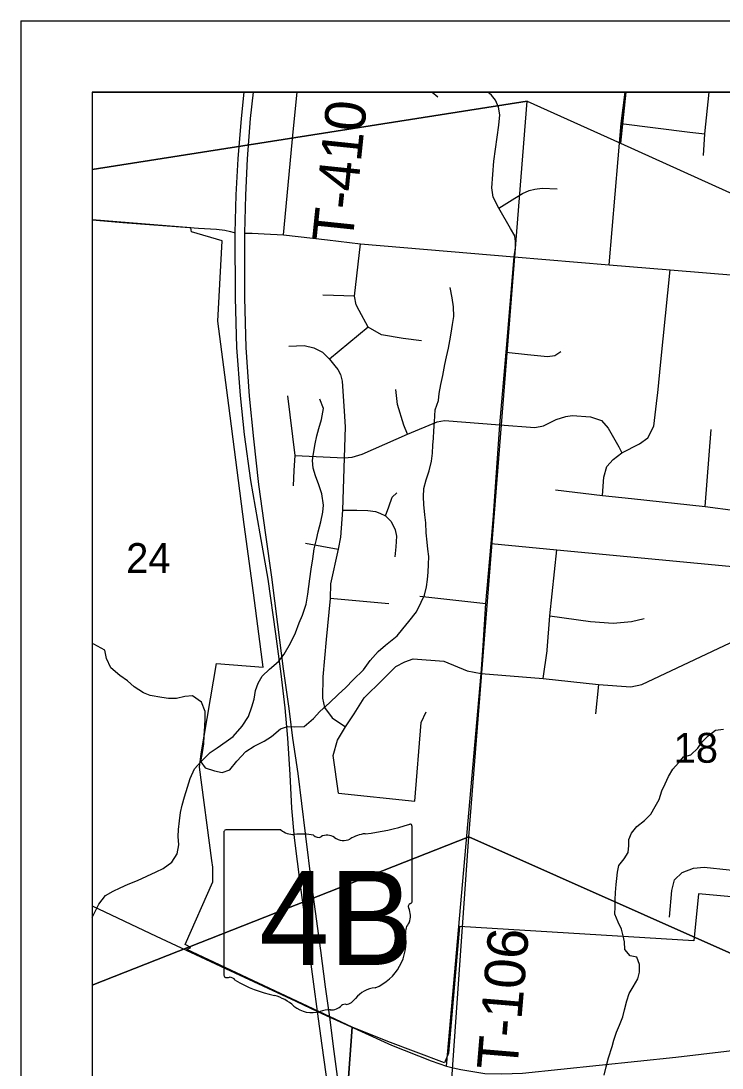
# Model space of a CAD drawing. Extents: x 0 to 34, y 0 to 22.
# Drawn here: x 2 to 2.983, y 19.532 to 21 of the extents above; entities that cross this region are included whole.
import ezdxf

# ---------------------------------------------------------------- set-up
doc = ezdxf.new("R2010")
doc.units = 0
for name, color, linetype in [('Default', 7, 'Continuous'), ('GM_X_County_Road', 7, 'Continuous'), ('GM_X_Minor_River', 7, 'Continuous'), ('GM_X_Section', 7, 'Continuous'), ('GM_X_Section_Text', 7, 'Continuous'), ('GM_X_State_Location', 7, 'Continuous'), ('GM_X_State_Route', 7, 'Continuous'), ('GM_X_State_Shield', 7, 'Continuous'), ('GM_X_Township_Road', 7, 'Continuous'), ('GM_X_Township_Road_Text', 7, 'Continuous'), ('SH_Cut_Line', 7, 'Continuous'), ('SH_Data', 7, 'Continuous')]:
    doc.layers.add(name, color=color, linetype=linetype)

msp = doc.modelspace()

# ---------------------------------------------------------------- linework, layer by layer
at = {"layer": 'Default'}
for points in [[(2.848, 20.9), (2.1, 20.9), (2.1, 20.7916), (2.7095, 20.8874), (2.8405, 20.8285)], [(3.8452, 20.9), (2.848, 20.9), (2.8405, 20.8285), (3.806, 20.3918)], [(2.1, 20.7916), (2.1, 19.6477), (2.6281, 19.856), (2.7095, 20.8874)]]:
    msp.add_lwpolyline(points, close=True, dxfattribs=at)
for points in [[(2.4657, 19.3633), (2.4543, 19.4479), (2.4643, 19.5889), (2.2326, 19.6977), (2.2384, 19.7007), (2.2301, 19.7049), (2.2689, 19.7927), (2.2692, 19.8013), (2.2689, 19.8136), (2.2677, 19.8229), (2.2505, 19.9535), (2.2526, 19.9723), (2.2744, 20.0988), (2.3397, 20.0939), (2.3259, 20.1979), (2.313, 20.2941), (2.2914, 20.4608), (2.2761, 20.579), (2.2821, 20.6918), (2.2391, 20.7041), (2.238, 20.7101), (2.1, 20.7213), (2.1, 19.3633)], [(2.5933, 19.3633), (2.6281, 19.856), (2.1, 19.6477), (2.1, 19.3633)], [(3.2168, 19.7517), (2.95, 19.7758), (2.9434, 19.7099), (2.6148, 19.7304), (2.5993, 19.5526), (2.5939, 19.5391), (2.5143, 19.569), (2.4643, 19.5889), (2.4543, 19.4479)]]:
    msp.add_lwpolyline(points, dxfattribs=at)
at = {"layer": 'GM_X_County_Road'}
for p, q in [((2.1, 20.7212), (2.143, 20.7174)), ((2.416, 19.6111), (2.433, 19.603)), ((2.433, 19.603), (2.4712, 19.5858))]:
    msp.add_line(p, q, dxfattribs=at)
for points in [[(2.143, 20.7174), (2.1677, 20.7153), (2.2489, 20.7094), (2.2744, 20.708), (2.286, 20.7066), (2.2939, 20.7047), (2.3004, 20.7028)], [(2.3138, 20.7026), (2.324, 20.7022), (2.3411, 20.7015), (2.3683, 20.7001), (2.4299, 20.6929)], [(2.4299, 20.6929), (2.4761, 20.6875), (2.6915, 20.6692), (2.8247, 20.6581)], [(2.8247, 20.6581), (2.9104, 20.6511), (3.1936, 20.6276), (3.2344, 20.6247), (3.2635, 20.6211), (3.2805, 20.6179), (3.3054, 20.6092), (3.3268, 20.6005), (3.4215, 20.5582), (3.4671, 20.5379), (3.6399, 20.4609), (3.6591, 20.4516), (3.6689, 20.4477), (3.679, 20.4455)], [(2.1, 19.7592), (2.1895, 19.7168), (2.287, 19.6714)], [(2.287, 19.6714), (2.3854, 19.6255), (2.416, 19.6111)], [(2.4712, 19.5858), (2.4721, 19.5853), (2.5194, 19.564), (2.5751, 19.5418), (2.5966, 19.5342), (2.6061, 19.5319)], [(2.6061, 19.5319), (2.6167, 19.5295), (2.6506, 19.5239), (2.6743, 19.5237), (2.703, 19.5246), (2.918, 19.5471), (3.06, 19.5636), (3.1002, 19.5668)]]:
    msp.add_lwpolyline(points, dxfattribs=at)
at = {"layer": 'GM_X_Minor_River'}
for points in [[(2.58, 20.4377), (2.5807, 20.4546), (2.5853, 20.4677), (2.5863, 20.4776), (2.5886, 20.49), (2.5917, 20.5028), (2.5944, 20.5183), (2.5967, 20.5289), (2.5993, 20.5413), (2.6012, 20.5515), (2.603, 20.5621), (2.6049, 20.5745), (2.6068, 20.5855), (2.6064, 20.5992), (2.6046, 20.6118), (2.602, 20.6263)], [(2.4216, 20.4413), (2.4241, 20.4564), (2.4192, 20.4695)], [(2.4234, 20.3111), (2.4244, 20.3209), (2.4218, 20.337), (2.4176, 20.3496), (2.413, 20.3623), (2.4099, 20.3727), (2.4086, 20.3838), (2.41, 20.3936), (2.4127, 20.4072), (2.4149, 20.4182), (2.4175, 20.4284), (2.4216, 20.4413)], [(2.2522, 19.961), (2.2584, 19.9525), (2.2712, 19.9487), (2.2822, 19.9461), (2.2929, 19.95), (2.3028, 19.9619), (2.3153, 19.9757), (2.3269, 19.983), (2.3412, 19.9902), (2.3512, 19.9964), (2.3641, 20.0075), (2.3737, 20.0106), (2.3839, 20.01), (2.3972, 20.0104), (2.4101, 20.0218), (2.4191, 20.0319), (2.4327, 20.044), (2.4448, 20.0555), (2.4553, 20.0651), (2.4659, 20.0759), (2.4804, 20.0899), (2.4895, 20.103), (2.5008, 20.1156), (2.5113, 20.1245), (2.5273, 20.1378), (2.5352, 20.1474), (2.5438, 20.1579), (2.5548, 20.1716), (2.5613, 20.1848), (2.5657, 20.1949), (2.5687, 20.2067), (2.5701, 20.2169), (2.5708, 20.2272), (2.5715, 20.2378), (2.5718, 20.2492), (2.5705, 20.2595), (2.5693, 20.2691), (2.5681, 20.2824), (2.5678, 20.2961), (2.5662, 20.3076), (2.565, 20.3217), (2.5642, 20.3327), (2.5649, 20.3445), (2.5679, 20.3566), (2.5724, 20.3691), (2.5755, 20.3827), (2.5769, 20.3941), (2.5776, 20.4051), (2.5786, 20.4149), (2.5789, 20.4252), (2.58, 20.4377)], [(2.1, 19.7426), (2.1091, 19.7617), (2.1186, 19.7736), (2.1294, 19.7798), (2.139, 19.7845), (2.1505, 19.7895), (2.1636, 19.7948), (2.1767, 19.8006), (2.1898, 19.8067), (2.1994, 19.8117), (2.2114, 19.8205), (2.219, 19.8321), (2.2212, 19.8446), (2.2204, 19.8565), (2.2207, 19.8663), (2.2222, 19.8785), (2.2236, 19.8902), (2.2262, 19.9004), (2.2295, 19.9118), (2.2333, 19.9254), (2.2371, 19.9378), (2.2432, 19.9514), (2.2522, 19.961), (2.2655, 19.9744), (2.2752, 19.9809), (2.2879, 19.9897), (2.2976, 19.9967), (2.3102, 20.0112), (2.3189, 20.0247), (2.3239, 20.0382), (2.3268, 20.0488), (2.329, 20.0609), (2.3324, 20.0715), (2.3384, 20.0812), (2.3485, 20.0908), (2.361, 20.1019), (2.3692, 20.112), (2.378, 20.1273), (2.3849, 20.142), (2.3902, 20.1559), (2.3947, 20.1668), (2.3997, 20.1823), (2.402, 20.1963), (2.4038, 20.2069), (2.4048, 20.2179), (2.4067, 20.2312), (2.409, 20.2456), (2.4109, 20.2596), (2.4143, 20.2729), (2.4169, 20.2838), (2.4203, 20.2978), (2.4234, 20.3111)], [(2.2522, 19.961), (2.2544, 19.9743), (2.2563, 19.9864), (2.257, 19.9982), (2.2577, 20.0107), (2.2584, 20.0214), (2.2583, 20.0316), (2.253, 20.0447), (2.2403, 20.0538), (2.23, 20.0529), (2.2181, 20.0498), (2.2067, 20.0501), (2.1973, 20.0512), (2.1814, 20.0543), (2.1716, 20.0579), (2.1589, 20.0663), (2.1493, 20.0745), (2.1388, 20.082), (2.1258, 20.0927), (2.1201, 20.1058), (2.1178, 20.1176), (2.102, 20.126), (2.1, 20.1271)], [(2.8176, 19.5216), (2.8206, 19.5333), (2.8237, 19.5461), (2.8287, 19.5619), (2.8312, 19.5706), (2.835, 19.5819), (2.8394, 19.592), (2.844, 19.6033), (2.8462, 19.6131), (2.8496, 19.6259), (2.8529, 19.6361), (2.8585, 19.6454), (2.8649, 19.6566), (2.8671, 19.666), (2.8674, 19.677), (2.8635, 19.687), (2.8541, 19.6889), (2.8467, 19.6978), (2.8463, 19.7085), (2.8443, 19.7173), (2.8419, 19.7265), (2.8372, 19.7361), (2.8326, 19.7473), (2.8333, 19.7579), (2.8332, 19.7678), (2.8335, 19.778), (2.8346, 19.789), (2.8356, 19.7977), (2.8363, 19.8065), (2.8381, 19.8159), (2.8456, 19.8252), (2.8511, 19.8341), (2.8522, 19.8436), (2.8521, 19.8524), (2.8561, 19.861), (2.8636, 19.8703), (2.8741, 19.8787), (2.8831, 19.8875), (2.8891, 19.8984), (2.8948, 19.9084), (2.8985, 19.9205), (2.903, 19.9302), (2.9079, 19.9407), (2.9139, 19.9508), (2.9221, 19.9597), (2.9288, 19.9682), (2.9392, 19.9709), (2.949, 19.9802), (2.9553, 19.9891), (2.9635, 19.9976), (2.9736, 20.0056), (2.9851, 20.0068)]]:
    msp.add_lwpolyline(points, dxfattribs=at)
at = {"layer": 'GM_X_Section'}
msp.add_lwpolyline([(2.7095, 20.8874), (2.8405, 20.8285), (3.806, 20.3918), (3.7257, 19.3674), (2.6281, 19.856)], close=True, dxfattribs=at)
msp.add_lwpolyline([(2.5933, 19.3633), (2.6281, 19.856), (3.7257, 19.3674), (3.7253, 19.3633)], dxfattribs=at)
at = {"layer": 'GM_X_State_Route'}
for points in [[(2.416, 19.6111), (2.4107, 19.6494), (2.4036, 19.7021), (2.392, 19.7883), (2.3837, 19.8543), (2.3798, 19.8963), (2.3774, 19.9434), (2.3743, 19.9941), (2.3703, 20.0368), (2.3646, 20.0846), (2.3573, 20.1404), (2.3464, 20.217), (2.3354, 20.2806), (2.3224, 20.3556), (2.3134, 20.4202), (2.3078, 20.4747), (2.3026, 20.5422), (2.3006, 20.6116), (2.3004, 20.7028), (2.3018, 20.7561), (2.3045, 20.8066), (2.3093, 20.8634), (2.3128, 20.9)], [(2.4129, 19.7512), (2.4078, 19.7888), (2.399, 19.8604), (2.3886, 19.9446), (2.381, 19.9942), (2.3762, 20.0358), (2.3683, 20.0917), (2.3602, 20.1535), (2.3516, 20.2202), (2.3435, 20.2792), (2.3336, 20.3501), (2.3264, 20.4142), (2.3206, 20.4737), (2.3159, 20.5421), (2.3139, 20.6115), (2.3138, 20.7026), (2.3151, 20.7559), (2.3178, 20.8065), (2.3219, 20.8632), (2.3259, 20.9)], [(2.4316, 19.6129), (2.427, 19.6456), (2.4203, 19.6967), (2.4129, 19.7512)], [(2.4541, 19.3633), (2.4449, 19.4144), (2.4331, 19.4862), (2.4223, 19.5631), (2.416, 19.6111)], [(2.4525, 19.4538), (2.4492, 19.4777), (2.4393, 19.5551), (2.433, 19.603), (2.4316, 19.6129)]]:
    msp.add_lwpolyline(points, dxfattribs=at)
at = {"layer": 'GM_X_State_Shield'}
for p, q in [((2.5483, 19.7659), (2.5483, 19.8706)), ((2.2846, 19.8622), (2.2846, 19.662)), ((2.3644, 19.8656), (2.2872, 19.8656)), ((2.5483, 19.7659), (2.5483, 19.7659))]:
    msp.add_line(p, q, dxfattribs=at)
for centre, radius, start, end in [((2.4544, 20.1384), 0.2796, 275.8445, 288.9065), ((2.5454, 19.871), 0.00294, 351.8621, 97.738), ((2.2876, 19.8626), 0.00305, 98.1301, 188.1301), ((2.3828, 19.8888), 0.0296, 231.6195, 271.1119), ((2.3926, 19.7533), 0.1064, 80.4867, 94.9883), ((2.4168, 19.8636), 0.00855, 219.7921, 297.1024), ((2.4293, 19.8405), 0.0178, 54.4667, 119.1411), ((2.4523, 19.8722), 0.0214, 233.8562, 294.8282), ((2.49, 19.8045), 0.0563, 97.3462, 120.7689), ((2.5452, 19.7655), 0.00314, 289.6038, 7.7341), ((2.5476, 19.7582), 0.00454, 107.944, 210.337), ((2.5187, 19.745), 0.0273, 340.033, 23.6496), ((2.5588, 19.7221), 0.0198, 136.8065, 186.9296), ((2.47, 19.7088), 0.0699, 292.3089, 8.9858), ((2.2877, 19.6616), 0.00308, 171.9584, 258.3066), ((2.2881, 19.6821), 0.0235, 267.339, 280.6039), ((2.2929, 19.6505), 0.00848, 29.7484, 93.2717), ((2.4, 19.8303), 0.2019, 240.4129, 257.1985), ((2.3398, 19.5721), 0.0632, 47.1842, 75.836), ((2.4995, 19.6059), 0.0383, 94.4031, 142.5768), ((2.4081, 19.6495), 0.0401, 230.7004, 286.2918), ((2.4342, 19.6345), 0.0214, 268.777, 315.5493), ((2.4536, 19.6151), 0.00601, 65.7517, 132.6484), ((2.451, 19.6427), 0.0226, 282.8732, 323.2771), ((2.4313, 19.5803), 0.0329, 85.6951, 111.2099)]:
    msp.add_arc(centre, radius, start, end, dxfattribs=at)
at = {"layer": 'GM_X_Township_Road'}
for p, q in [((2.5765, 20.9), (2.5843, 20.8938)), ((2.8416, 20.856), (2.9376, 20.8442)), ((2.9376, 20.8442), (2.9589, 20.8416)), ((2.4675, 20.6141), (2.4234, 20.6153)), ((2.4867, 20.5704), (2.4327, 20.5256)), ((2.9591, 20.3192), (2.9677, 20.4273)), ((2.3989, 20.2676), (2.4447, 20.2592)), ((2.5156, 20.1827), (2.4333, 20.1903)), ((2.5591, 20.1936), (2.6518, 20.1832)), ((2.8097, 20.0697), (2.8054, 20.0282)), ((2.4454, 19.917), (2.5522, 19.9061))]:
    msp.add_line(p, q, dxfattribs=at)
for points in [[(3.7103, 19.3633), (3.7228, 19.5162), (3.8114, 20.3941), (3.8135, 20.4321), (3.8191, 20.5134), (3.8272, 20.6073), (3.8479, 20.9), (2.1, 20.9), (2.1, 18.801)], [(2.3683, 20.7001), (2.3817, 20.8447), (2.3873, 20.9)], [(2.6915, 20.6692), (2.6935, 20.682), (2.6935, 20.6907), (2.6922, 20.6988), (2.6864, 20.7089), (2.6702, 20.7376), (2.6622, 20.7527), (2.6601, 20.7659), (2.6632, 20.8033), (2.6702, 20.8539), (2.6713, 20.8685), (2.6697, 20.879), (2.6654, 20.8888), (2.6598, 20.8957), (2.6545, 20.9)], [(2.8247, 20.6581), (2.8416, 20.856), (2.847, 20.9)], [(2.957, 20.8111), (2.9589, 20.8416), (2.965, 20.9)], [(2.6702, 20.7376), (2.6923, 20.7517), (2.7031, 20.758), (2.7125, 20.7622), (2.7205, 20.7642), (2.7306, 20.7656), (2.752, 20.7645)], [(2.5614, 20.5515), (2.536, 20.5548), (2.5054, 20.5597), (2.4867, 20.5704), (2.4743, 20.5942), (2.4698, 20.6021), (2.4675, 20.6141), (2.4761, 20.6875)], [(2.6623, 20.3065), (2.6715, 20.4337), (2.6805, 20.5355), (2.6915, 20.6692)], [(2.8922, 20.4713), (2.8931, 20.4783), (2.8969, 20.5221), (2.9104, 20.6511)], [(2.3755, 20.544), (2.397, 20.5447), (2.4106, 20.5417), (2.4229, 20.5354), (2.4327, 20.5256), (2.44, 20.5162), (2.4441, 20.5113), (2.4479, 20.504), (2.4502, 20.4948), (2.4533, 20.453), (2.4545, 20.431), (2.453, 20.3876), (2.4508, 20.314), (2.4481, 20.276), (2.4447, 20.2592), (2.4342, 20.2109), (2.4333, 20.1903), (2.4279, 20.1327), (2.4232, 20.0802), (2.4228, 20.0502), (2.4258, 20.0374), (2.4364, 20.023), (2.4552, 20.0102)], [(2.6805, 20.5355), (2.7102, 20.5321), (2.7383, 20.5293), (2.7486, 20.5309), (2.7571, 20.5363)], [(2.542, 20.4207), (2.5368, 20.4331), (2.5279, 20.4623), (2.5256, 20.4831)], [(2.3819, 20.3482), (2.383, 20.3697), (2.3846, 20.3907), (2.374, 20.4742)], [(2.8154, 20.3346), (2.8173, 20.3603), (2.8214, 20.3754), (2.8305, 20.3852), (2.8425, 20.3942), (2.8674, 20.407), (2.8791, 20.4154), (2.8874, 20.4319), (2.8922, 20.4713)], [(2.3846, 20.3907), (2.453, 20.3876), (2.4643, 20.3882), (2.4784, 20.3923), (2.542, 20.4207), (2.5836, 20.438), (2.5937, 20.4397), (2.6715, 20.4337)], [(2.6715, 20.4337), (2.7204, 20.4297), (2.7328, 20.4323), (2.7503, 20.441), (2.7637, 20.4455), (2.773, 20.4467), (2.7984, 20.4448), (2.8139, 20.4395), (2.8233, 20.4289), (2.8384, 20.4029), (2.8425, 20.3942)], [(2.5113, 20.306), (2.5157, 20.3188), (2.5205, 20.3322), (2.5272, 20.3383)], [(2.7494, 20.3425), (2.8154, 20.3346), (2.8561, 20.3302), (2.9591, 20.3192), (3.002, 20.3137), (3.0775, 20.3071), (3.1118, 20.3033), (3.1295, 20.3063), (3.1412, 20.3116), (3.1657, 20.3418)], [(2.4508, 20.314), (2.4711, 20.3139), (2.4864, 20.3133), (2.4969, 20.3122), (2.5033, 20.3099), (2.5113, 20.306), (2.519, 20.2981), (2.5246, 20.2862), (2.5263, 20.2775), (2.5257, 20.2628), (2.5241, 20.2484)], [(2.6478, 20.1243), (2.6518, 20.1832), (2.6594, 20.2674), (2.6623, 20.3065)], [(2.6594, 20.2674), (2.7513, 20.2584), (2.9928, 20.2354), (3.0002, 20.2347), (3.0311, 20.2332), (3.0681, 20.2437)], [(2.7377, 20.1179), (2.7415, 20.1656), (2.7513, 20.2584)], [(2.6451, 20.0849), (2.732, 20.078), (2.8097, 20.0697), (2.8552, 20.0664), (2.8704, 20.0694), (3.0191, 20.1396), (3.1804, 20.2184), (3.1823, 20.2191)], [(2.7415, 20.1656), (2.7983, 20.158), (2.8301, 20.1556), (2.8559, 20.158), (2.8737, 20.162)], [(2.5966, 19.5342), (2.6451, 20.0849), (2.6478, 20.1243)], [(2.732, 20.078), (2.7376, 20.1169), (2.7377, 20.1179)], [(2.4454, 19.917), (2.4379, 19.9702), (2.4439, 19.9917), (2.4552, 20.0102), (2.4671, 20.0284), (2.4813, 20.0506), (2.5069, 20.0762), (2.5254, 20.0947), (2.538, 20.1015), (2.5501, 20.1053), (2.5929, 20.1023), (2.6254, 20.0886), (2.6451, 20.0849)], [(2.5522, 19.9061), (2.5612, 20.0163), (2.568, 20.031)], [(2.9094, 19.7434), (2.9127, 19.7808), (2.9165, 19.7956), (2.927, 19.8061), (2.9429, 19.8122), (2.9577, 19.8133), (2.9928, 19.8097), (3.2202, 19.7881), (3.2796, 19.7832), (3.4192, 19.7737), (3.5185, 19.7662), (3.5942, 19.7605), (3.7377, 19.7503)]]:
    msp.add_lwpolyline(points, dxfattribs=at)
at = {"layer": 'SH_Cut_Line'}
msp.add_lwpolyline([(8.9, 14.8595), (8.9, 20.9), (2.1, 20.9), (2.1, 19.3633)], dxfattribs=at)
at = {"layer": 'SH_Data'}
for p, q in [((2, 21), (9, 21)), ((2, 21), (2, 14)), ((2.1, 20.9), (2.1, 14.1)), ((2.1, 20.9), (8.9, 20.9))]:
    msp.add_line(p, q, dxfattribs=at)

# ---------------------------------------------------------------- texts
at = {"layer": 'GM_X_Section_Text'}
for s, p in [('24', (2.1475, 20.2259)), ('18', (2.915, 19.9598))]:
    msp.add_text(s, height=0.04186, rotation=0, dxfattribs=at).set_placement(p)
at = {"layer": 'GM_X_State_Location'}
for s in ['s', 'r']:
    msp.add_text(s, height=0.000189, dxfattribs=at).set_placement((2.4135, 19.7488))
msp.add_text('4B', height=0.000189, rotation=0, dxfattribs=at).set_placement((2.36, 19.735))
at = {"layer": 'GM_X_State_Shield'}
msp.add_text('4B', height=0.13184, dxfattribs=at).set_placement((2.3341, 19.6762))
at = {"layer": 'GM_X_Township_Road_Text'}
for s, rotation, p in [('T-410', 84.0648, (2.4647, 20.6879)), ('T-106', 85.213, (2.6957, 19.5273))]:
    msp.add_text(s, height=0.05682, rotation=rotation, dxfattribs=at).set_placement(p)

doc.saveas('drawing.dxf')
